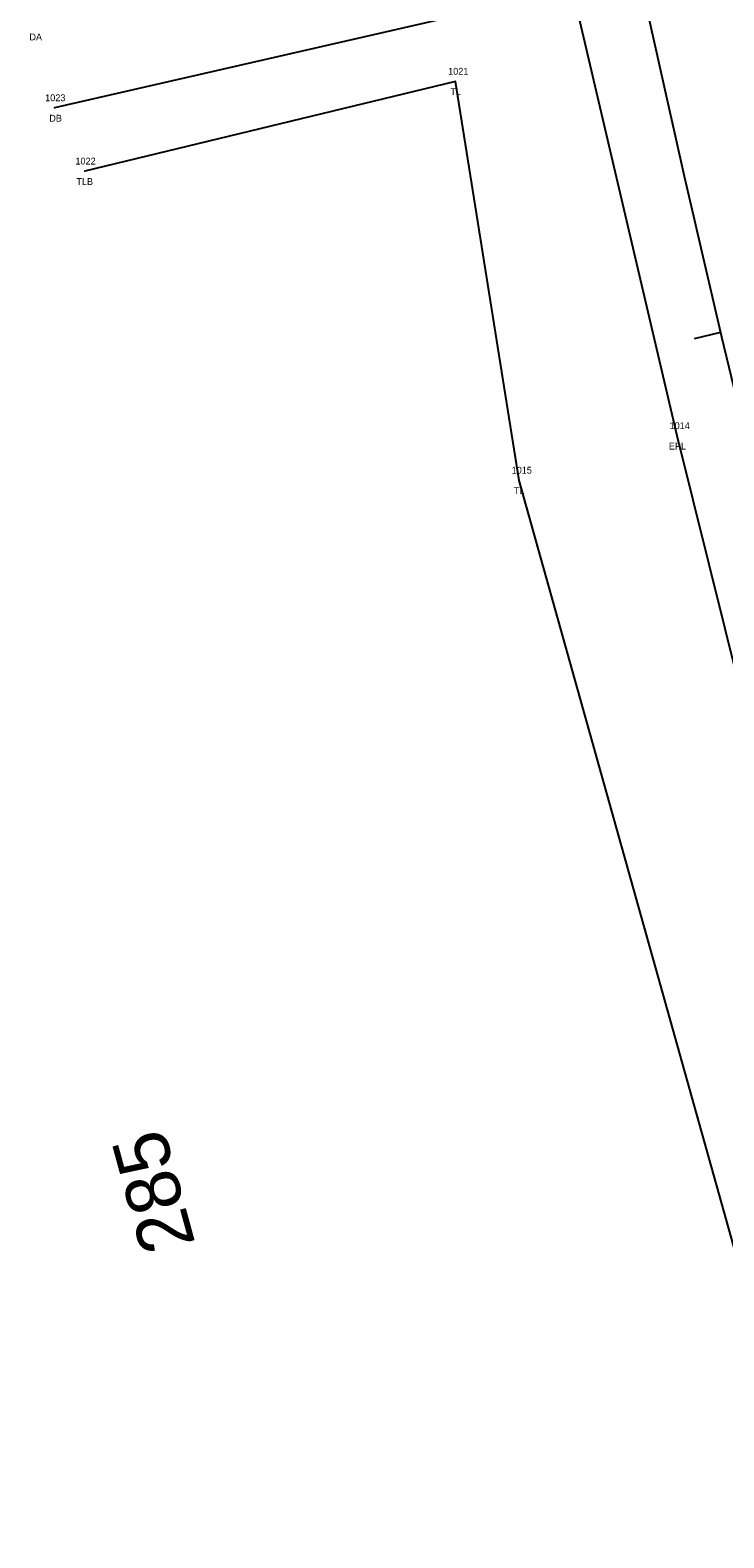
# Model space of a CAD drawing. Extents: x 2445178 to 2446205, y 790762 to 792372.
# Drawn here: x 2445664.3 to 2445766.2, y 791332.4 to 791553.8 of the extents above; entities that cross this region are included whole.
import ezdxf

# ---------------------------------------------------------------- set-up
doc = ezdxf.new("R2010")
doc.units = 0
for name, color, linetype in [('RD_EX_Driveway', 7, 'Continuous'), ('RD_EX_Driveway_txCode', 7, 'Continuous'), ('RD_EX_Road', 7, 'Continuous'), ('RD_EX_Road_txCode', 7, 'Continuous'), ('RD_EX_VEG', 7, 'Continuous'), ('RD_EX_VEG_txCode', 7, 'Continuous'), ('RD_HC_Cl', 7, 'Continuous'), ('RD_HC_Data_Tic', 7, 'Continuous'), ('RD_HC_TX_Sta50', 7, 'Continuous'), ('RD_SMD_Locator', 7, 'Continuous')]:
    doc.layers.add(name, color=color, linetype=linetype)

msp = doc.modelspace()

# ---------------------------------------------------------------- linework, layer by layer
at = {"layer": 'RD_EX_Driveway'}
msp.add_line((2445744.01, 791559.83), (2445667.9, 791542.37), dxfattribs=at)
at = {"layer": 'RD_EX_Road'}
msp.add_lwpolyline([(2445850.42, 791174.36), (2445823.13, 791264.7), (2445806.34, 791321.46), (2445789.41, 791379.89), (2445773.46, 791437.57), (2445759.36, 791494.22), (2445744.01, 791559.83), (2445740.09, 791577.64), (2445731.05, 791621.01), (2445722.21, 791669.43), (2445711, 791738.26), (2445706.49, 791765.2), (2445707.32, 791765.82), (2445706.36, 791771.19), (2445705.53, 791771.38), (2445701.96, 791795.92), (2445699.57, 791813.34), (2445693.24, 791870.48), (2445688.14, 791921.92), (2445683.42, 791987.19), (2445680.88, 792033.67), (2445678.74, 792090.55), (2445675.91, 792199.23), (2445673.61, 792301.11)], dxfattribs=at)
at = {"layer": 'RD_EX_VEG'}
msp.add_lwpolyline([(2445828.32, 791169.91), (2445768.75, 791371.54), (2445736.16, 791487.68), (2445726.82, 791546.26), (2445672.34, 791533.07)], dxfattribs=at)
at = {"layer": 'RD_HC_Cl'}
msp.add_arc((2448553.48, 792169.37), 2864.79, 181.3527, 196.84356, dxfattribs=at)
at = {"layer": 'RD_HC_Data_Tic'}
msp.add_line((2445765.75, 791509.42), (2445761.85, 791508.49), dxfattribs=at)
at = {"layer": 'RD_SMD_Locator'}
for centre in [(2445726.82, 791546.26), (2445667.9, 791542.37), (2445672.34, 791533.07), (2445759.36, 791494.22), (2445736.16, 791487.68)]:
    msp.add_circle(centre, 0.001, dxfattribs=at)

# ---------------------------------------------------------------- texts
at = {"layer": 'RD_EX_Driveway_txCode'}
for s, p in [('DA', (2445664.2, 791552.3)), ('1023', (2445666.52, 791543.37)), ('DB', (2445667.12, 791540.37))]:
    msp.add_text(s, height=1, dxfattribs=at).set_placement(p)
at = {"layer": 'RD_EX_Road_txCode'}
for s, p in [('1014', (2445758.26, 791495.22)), ('EPL', (2445758.15, 791492.22))]:
    msp.add_text(s, height=1, dxfattribs=at).set_placement(p)
at = {"layer": 'RD_EX_VEG_txCode'}
for s, p in [('1021', (2445725.72, 791547.26)), ('TL', (2445726.05, 791544.26)), ('1022', (2445670.96, 791534.07)), ('TLB', (2445671.1, 791531.07)), ('1015', (2445735.05, 791488.68)), ('TL', (2445735.38, 791485.68))]:
    msp.add_text(s, height=1, dxfattribs=at).set_placement(p)
at = {"layer": 'RD_HC_TX_Sta50'}
msp.add_text('285', height=8, rotation=105.3186, dxfattribs=at).set_placement((2445688.61, 791375.61))

doc.saveas('drawing.dxf')
